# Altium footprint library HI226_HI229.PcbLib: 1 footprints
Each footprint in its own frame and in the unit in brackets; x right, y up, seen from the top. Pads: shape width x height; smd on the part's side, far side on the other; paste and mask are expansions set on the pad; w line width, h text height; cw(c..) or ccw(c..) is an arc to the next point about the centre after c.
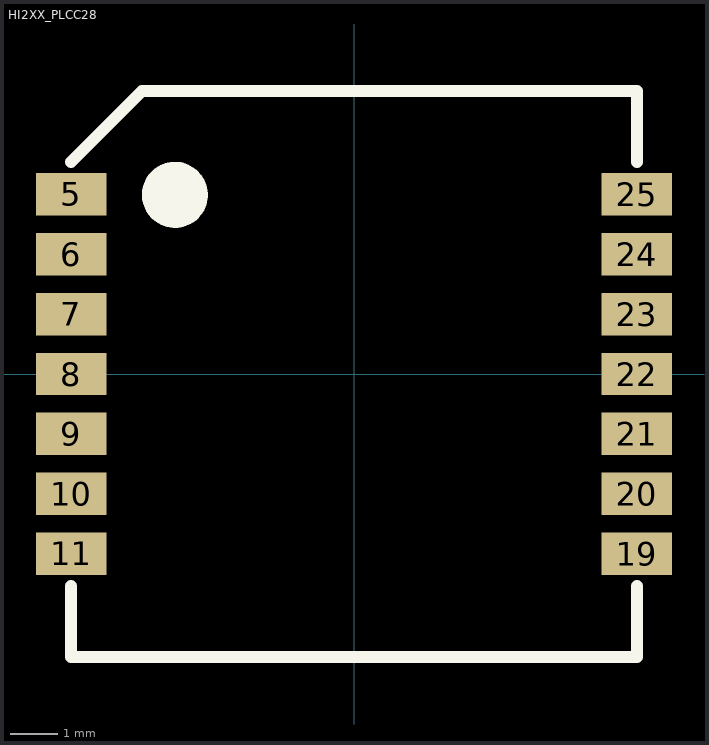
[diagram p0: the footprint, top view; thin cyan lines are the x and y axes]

## HI2XX_PLCC28 [mm]
pads (14):
  rect 1.5x0.9 smd: 5(-6,3.81) 6(-6,2.54) 7(-6,1.27) 8(-6,0) 9(-6,-1.27) 10(-6,-2.54) 11(-6,-3.81) 19(6,-3.81) 20(6,-2.54) 21(6,-1.27) 22(6,0) 23(6,1.27) 24(6,2.54) 25(6,3.81)
Top Overlay:
  circle w0.7: c-3.8,3.8 r0.35
  lines w0.254: -6,-4.5 -6,-6 -4.5,-6 6,-6 6,-4.5 ; -6,4.5 -4.5,6 6,6 6,4.5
